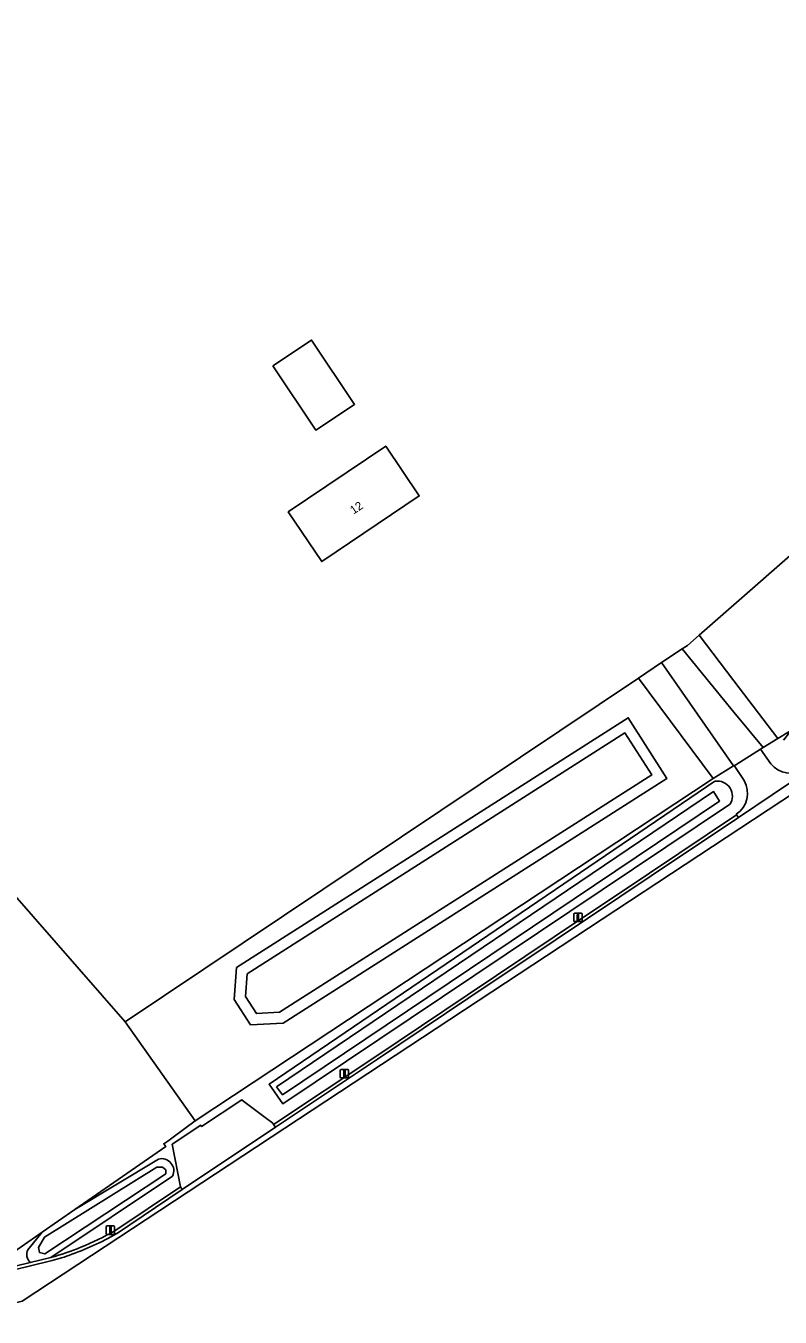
# Model space of a CAD drawing. Extents: x 156502 to 159075, y 384229 to 386100.
# Drawn here: x 158415.4 to 158505.5, y 384265.4 to 384419.7 of the extents above; entities that cross this region are included whole.
import ezdxf

# ---------------------------------------------------------------- set-up
doc = ezdxf.new("R2010")
doc.units = 0
for name, color, linetype in [('IMGEO_Berm_groen', 7, 'Continuous'), ('IMGEO_Gemengd_bos', 7, 'Continuous'), ('IMGEO_Grasland_overig', 7, 'Continuous'), ('IMGEO_Groenvoorziening', 7, 'Continuous'), ('IMGEO_Hek', 7, 'Continuous'), ('IMGEO_Lichtmast', 7, 'Continuous'), ('IMGEO_Loofbos', 7, 'Continuous'), ('IMGEO_Oever', 7, 'Continuous'), ('IMGEO_Pand', 7, 'Continuous'), ('IMGEO_Pand_nummerreeks', 7, 'Continuous'), ('IMGEO_Rijbaan_lokaal_gesloten', 7, 'Continuous'), ('IMGEO_Rijbaan_lokaal_halfverhard', 7, 'Continuous'), ('IMGEO_Rijbaan_lokaal_open', 7, 'Continuous'), ('IMGEO_Waterloop', 7, 'Continuous')]:
    doc.layers.add(name, color=color, linetype=linetype)

msp = doc.modelspace()

# ---------------------------------------------------------------- linework, layer by layer
at = {"layer": 'IMGEO_Berm_groen'}
for points in [[(158501.22, 384329.54), (158500.02, 384331.33), (158499.95, 384331.29), (158497.53, 384329.78), (158435.63, 384288.89), (158435.15, 384288.53), (158434.85, 384288.31), (158432.37, 384286.47), (158431.87, 384286.14), (158432.11, 384285.8), (158421.25, 384278.29), (158431.23, 384284.32)], [(158444.44, 384293.26), (158497.73, 384329.47)], [(158499.48, 384326.68), (158446.11, 384290.9), (158444.44, 384293.26)], [(158457.2, 384296.58), (158468.1, 384303.9), (158478.52, 384310.87), (158489.9, 384318.5), (158500.3, 384325.46), (158500.27, 384325.52)], [(158426.03, 384275.74), (158433.85, 384280.99), (158433.88, 384281.01), (158432.85, 384286.08), (158436.28, 384288.36), (158436.39, 384288.2), (158441.18, 384291.39), (158441.42, 384291.21), (158443.84, 384289.39), (158444.89, 384288.59), (158444.99, 384288.46), (158457.2, 384296.58)], [(158432.91, 384282.29), (158418.39, 384272.56)]]:
    msp.add_lwpolyline(points, dxfattribs=at)
for centre, radius, start, end in [((158498.02, 384327.7), 1.79, 325.0453, 99.1903), ((158498.6, 384328.04), 3.02, 303.4638, 29.7821), ((158431.6, 384282.91), 1.46, 334.556, 104.5546), ((158409.55, 384304.56), 33.19, 291.9275, 299.7688), ((158409.54, 384304.51), 33.15, 285.4732, 291.9749)]:
    msp.add_arc(centre, radius, start, end, dxfattribs=at)
at = {"layer": 'IMGEO_Gemengd_bos'}
msp.add_lwpolyline([(158378.03, 384357.05), (158427.25, 384300.73), (158488.58, 384341.8), (158491.32, 384343.65), (158493.82, 384345.29), (158494.46, 384345.69), (158495.84, 384346.91), (158500, 384350.54), (158541.01, 384386.46), (158573.19, 384414.32), (158670.56, 384500)], dxfattribs=at)
for points in [[(158444.9, 384379.1), (158449.53, 384382.18), (158454.66, 384374.5), (158450.04, 384371.41)], [(158458.38, 384369.51), (158462.39, 384363.57), (158450.74, 384355.71), (158446.73, 384361.65)]]:
    msp.add_lwpolyline(points, close=True, dxfattribs=at)
at = {"layer": 'IMGEO_Grasland_overig'}
msp.add_lwpolyline([(158493.82, 384345.29), (158491.32, 384343.65), (158499.95, 384331.29), (158500.02, 384331.33), (158500.2, 384331.44), (158503.18, 384333.29), (158503.28, 384333.36), (158503.48, 384333.48), (158500, 384337.74)], close=True, dxfattribs=at)
at = {"layer": 'IMGEO_Groenvoorziening'}
for points in [[(158415.64, 384273.48), (158417.33, 384275.58), (158412.28, 384272.08), (158369.4, 384300.97), (158363.15, 384305.15), (158355.76, 384308.75), (158353, 384310.09), (158330.57, 384320.99), (158316.87, 384327), (158310.78, 384329.66), (158301.4, 384333.78), (158224.68, 384367.19), (158139.02, 384415.66), (158112.87, 384430.01), (158110.98, 384431.04), (158010.38, 384485.78)], [(158505.9, 384334.39), (158506.68, 384335.32), (158506.55, 384335.39), (158505.25, 384334.58), (158503.48, 384333.48), (158503.28, 384333.36), (158503.18, 384333.29), (158504.41, 384331.54)], [(158384.23, 384284.06), (158389.27, 384280.37), (158399.37, 384272.71), (158404.11, 384269.44), (158404.62, 384269.18), (158407.37, 384269.88), (158415.91, 384271.95)]]:
    msp.add_lwpolyline(points, dxfattribs=at)
for points in [[(158584.38, 384386.89), (158587.8, 384389.16), (158587.72, 384389.57), (158587.44, 384391.07), (158586.13, 384393.74), (158574.92, 384411.58), (158573.19, 384414.32), (158541.01, 384386.46), (158500, 384350.54), (158495.84, 384346.91), (158500, 384341.46), (158505.25, 384334.58), (158506.55, 384335.39), (158506.68, 384335.32)], [(158505.25, 384334.58), (158500, 384341.46), (158495.84, 384346.91), (158494.46, 384345.69), (158493.82, 384345.29), (158500, 384337.74), (158503.48, 384333.48)], [(158499.95, 384331.29), (158491.32, 384343.65), (158488.58, 384341.8), (158497.53, 384329.78)], [(158497.53, 384329.78), (158488.58, 384341.8), (158427.25, 384300.73), (158435.63, 384288.89)], [(158440.54, 384307.2), (158487.36, 384337.06), (158491.99, 384329.81), (158446.13, 384300.57), (158442.23, 384300.34), (158440.29, 384303.39)]]:
    msp.add_lwpolyline(points, close=True, dxfattribs=at)
for centre, radius, start, end in [((158506.74, 384333.41), 2.98, 218.6163, 303.3303), ((158416.81, 384272.9), 1.31, 153.4915, 226.6054)]:
    msp.add_arc(centre, radius, start, end, dxfattribs=at)
at = {"layer": 'IMGEO_Hek'}
for points in [[(158495.84, 384346.91), (158500, 384350.54), (158541.01, 384386.46), (158573.19, 384414.32)], [(158500, 384341.46), (158495.84, 384346.91)], [(158491.32, 384343.65), (158488.58, 384341.8)], [(158427.25, 384300.73), (158488.58, 384341.8)], [(158497.53, 384329.78), (158488.58, 384341.8)], [(158500, 384341.46), (158505.25, 384334.58)], [(158505.25, 384334.58), (158503.48, 384333.48)], [(158506.68, 384335.32), (158506.55, 384335.39), (158505.25, 384334.58)], [(158503.28, 384333.36), (158503.18, 384333.29), (158500.2, 384331.44)], [(158503.48, 384333.48), (158503.28, 384333.36)], [(158497.53, 384329.78), (158499.95, 384331.29)], [(158500.2, 384331.44), (158500.02, 384331.33), (158499.95, 384331.29)], [(158421.25, 384278.29), (158432.11, 384285.8), (158431.87, 384286.14), (158432.37, 384286.47), (158434.85, 384288.31), (158435.15, 384288.53), (158435.63, 384288.89), (158497.53, 384329.78)], [(158435.63, 384288.89), (158427.25, 384300.73)], [(158417.33, 384275.58), (158421.25, 384278.29)], [(158412.28, 384272.08), (158417.33, 384275.58)]]:
    msp.add_lwpolyline(points, dxfattribs=at)
at = {"layer": 'IMGEO_Lichtmast'}
for p, q in [((158480.86, 384312.79), (158480.86, 384313.59)), ((158480.86, 384313.59), (158480.86, 384312.79)), ((158480.96, 384313.69), (158481.75, 384313.69)), ((158481.75, 384313.69), (158480.96, 384313.69)), ((158481.75, 384312.69), (158480.96, 384312.69)), ((158480.96, 384312.69), (158481.75, 384312.69)), ((158481.85, 384313.59), (158481.85, 384312.79)), ((158481.85, 384312.79), (158481.85, 384313.59)), ((158452.96, 384294.11), (158452.96, 384294.9)), ((158452.96, 384294.9), (158452.96, 384294.11)), ((158453.06, 384295), (158453.85, 384295)), ((158453.85, 384295), (158453.06, 384295)), ((158453.95, 384294.9), (158453.95, 384294.11)), ((158453.95, 384294.11), (158453.95, 384294.9)), ((158453.85, 384294.01), (158453.06, 384294.01)), ((158453.06, 384294.01), (158453.85, 384294.01)), ((158424.99, 384275.42), (158424.99, 384276.22)), ((158424.99, 384276.22), (158424.99, 384275.42)), ((158425.09, 384276.32), (158425.88, 384276.32)), ((158425.88, 384276.32), (158425.09, 384276.32)), ((158425.98, 384276.22), (158425.98, 384275.42)), ((158425.98, 384275.42), (158425.98, 384276.22)), ((158425.88, 384275.32), (158425.09, 384275.32)), ((158425.09, 384275.32), (158425.88, 384275.32))]:
    msp.add_line(p, q, dxfattribs=at)
for points in [[(158481.28, 384313.56), (158481.43, 384313.56), (158481.43, 384312.81), (158481.28, 384312.81), (158481.28, 384313.56)], [(158453.38, 384294.88), (158453.53, 384294.88), (158453.53, 384294.13), (158453.38, 384294.13), (158453.38, 384294.88)], [(158425.41, 384276.2), (158425.56, 384276.2), (158425.56, 384275.45), (158425.41, 384275.45), (158425.41, 384276.2)]]:
    msp.add_lwpolyline(points, dxfattribs=at)
for centre, start, end in [((158480.96, 384313.59), 90, 180), ((158480.96, 384313.59), 90, 180), ((158480.96, 384312.79), 180, 270), ((158480.96, 384312.79), 180, 270), ((158481.75, 384313.59), 0, 90), ((158481.75, 384313.59), 360, 90), ((158481.75, 384312.79), 270, 0), ((158481.75, 384312.79), 270, 0), ((158453.06, 384294.9), 90, 180), ((158453.06, 384294.9), 90, 180), ((158453.06, 384294.11), 180, 270), ((158453.06, 384294.11), 180, 270), ((158453.85, 384294.9), 0, 90), ((158453.85, 384294.9), 360, 90), ((158453.85, 384294.11), 270, 0), ((158453.85, 384294.11), 270, 0), ((158425.09, 384276.22), 90, 180), ((158425.09, 384276.22), 90, 180), ((158425.88, 384276.22), 0, 90), ((158425.88, 384276.22), 360, 90), ((158425.09, 384275.42), 180, 270), ((158425.09, 384275.42), 180, 270), ((158425.88, 384275.42), 270, 0), ((158425.88, 384275.42), 270, 0)]:
    msp.add_arc(centre, 0.1, start, end, dxfattribs=at)
at = {"layer": 'IMGEO_Loofbos'}
msp.add_lwpolyline([(158412.28, 384272.08), (158417.33, 384275.58), (158421.25, 384278.29), (158432.11, 384285.8), (158431.87, 384286.14), (158432.37, 384286.47), (158434.85, 384288.31), (158435.15, 384288.53), (158435.63, 384288.89), (158427.25, 384300.73), (158378.03, 384357.05)], dxfattribs=at)
at = {"layer": 'IMGEO_Oever'}
for points in [[(158440.54, 384307.2), (158440.29, 384303.39), (158442.23, 384300.34), (158446.13, 384300.57), (158491.99, 384329.81), (158487.36, 384337.06)], [(158441.81, 384306.45), (158486.96, 384335.24), (158490.17, 384330.22), (158445.71, 384301.87), (158442.93, 384301.7), (158441.63, 384303.73)], [(158445.35, 384292.94), (158497.56, 384328.24), (158498.28, 384327.1), (158446.07, 384292)], [(158417.63, 384275), (158431.03, 384283.35), (158431.73, 384283.35), (158432.11, 384283.01), (158432.11, 384282.57), (158417.65, 384272.99), (158417, 384273.16), (158416.9, 384273.75)]]:
    msp.add_lwpolyline(points, close=True, dxfattribs=at)
for points in [[(158497.73, 384329.47), (158444.44, 384293.26), (158446.11, 384290.9), (158499.48, 384326.68)], [(158431.23, 384284.32), (158421.25, 384278.29), (158417.33, 384275.58), (158415.64, 384273.48)], [(158415.91, 384271.95), (158418.39, 384272.56), (158432.91, 384282.29)]]:
    msp.add_lwpolyline(points, dxfattribs=at)
for centre, radius, start, end in [((158498.02, 384327.7), 1.79, 325.0453, 99.1903), ((158431.6, 384282.91), 1.46, 334.556, 104.5546), ((158416.81, 384272.9), 1.31, 153.4915, 226.6054)]:
    msp.add_arc(centre, radius, start, end, dxfattribs=at)
at = {"layer": 'IMGEO_Pand'}
for points in [[(158444.9, 384379.1), (158450.04, 384371.41), (158454.66, 384374.5), (158449.53, 384382.18)], [(158450.74, 384355.71), (158462.39, 384363.57), (158458.38, 384369.51), (158446.73, 384361.65)]]:
    msp.add_lwpolyline(points, close=True, dxfattribs=at)
at = {"layer": 'IMGEO_Rijbaan_lokaal_gesloten'}
for points in [[(158543.65, 384352.09), (158542.79, 384353.39), (158532.53, 384346.56), (158521.79, 384339.38), (158508.58, 384330.54), (158500.53, 384325.13), (158490.12, 384318.17), (158478.74, 384310.54), (158468.33, 384303.57), (158457.42, 384296.24), (158445.21, 384288.12), (158434.07, 384280.66), (158426.23, 384275.4)], [(158407.35, 384265.42), (158412.42, 384266.69), (158414.94, 384267.32), (158543.65, 384352.09)], [(158418.22, 384272.1), (158407.46, 384269.49), (158404.77, 384268.81), (158404.62, 384269.18), (158404.11, 384269.44), (158400.41, 384268.15), (158400.38, 384267.91), (158400.32, 384267.46), (158397.14, 384266.24)]]:
    msp.add_lwpolyline(points, dxfattribs=at)
for centre, radius, start, end in [((158409.43, 384304.82), 33.88, 289.1007, 299.7359), ((158409.57, 384304.41), 33.45, 284.99, 289.0995)]:
    msp.add_arc(centre, radius, start, end, dxfattribs=at)
at = {"layer": 'IMGEO_Rijbaan_lokaal_halfverhard'}
msp.add_lwpolyline([(158500.53, 384325.13), (158500.3, 384325.46), (158489.9, 384318.5), (158478.52, 384310.87), (158468.1, 384303.9), (158457.2, 384296.58), (158444.99, 384288.46), (158445.21, 384288.12), (158457.42, 384296.24), (158468.33, 384303.57), (158478.74, 384310.54), (158490.12, 384318.17)], close=True, dxfattribs=at)
for points in [[(158434.07, 384280.66), (158433.88, 384280.99), (158433.88, 384281.01), (158433.85, 384280.99), (158426.03, 384275.74)], [(158426.23, 384275.4), (158434.07, 384280.66)], [(158418.39, 384272.56), (158415.91, 384271.95), (158407.37, 384269.88), (158404.62, 384269.18), (158404.77, 384268.81), (158407.46, 384269.49), (158418.22, 384272.1)]]:
    msp.add_lwpolyline(points, dxfattribs=at)
for centre, radius, start, end in [((158409.55, 384304.56), 33.19, 291.9275, 299.7688), ((158409.43, 384304.82), 33.88, 289.1007, 299.7359), ((158409.57, 384304.41), 33.45, 284.99, 289.0995), ((158409.54, 384304.51), 33.15, 285.4732, 291.9749)]:
    msp.add_arc(centre, radius, start, end, dxfattribs=at)
at = {"layer": 'IMGEO_Rijbaan_lokaal_open'}
for points in [[(158504.41, 384331.54), (158503.18, 384333.29), (158500.2, 384331.44), (158500.02, 384331.33), (158501.22, 384329.54)], [(158500.27, 384325.52), (158500.3, 384325.46), (158500.53, 384325.13), (158508.58, 384330.54), (158508.39, 384330.9), (158508.38, 384330.91)]]:
    msp.add_lwpolyline(points, dxfattribs=at)
msp.add_lwpolyline([(158445.21, 384288.12), (158444.99, 384288.46), (158444.89, 384288.59), (158443.84, 384289.39), (158441.42, 384291.21), (158441.18, 384291.39), (158436.39, 384288.2), (158436.28, 384288.36), (158432.85, 384286.08), (158433.88, 384281.01), (158433.88, 384280.99), (158434.07, 384280.66)], close=True, dxfattribs=at)
for centre, radius, start, end in [((158506.74, 384333.41), 2.98, 218.6163, 303.3303), ((158498.6, 384328.04), 3.02, 303.4638, 29.7821)]:
    msp.add_arc(centre, radius, start, end, dxfattribs=at)
at = {"layer": 'IMGEO_Waterloop'}
for points in [[(158441.81, 384306.45), (158441.63, 384303.73), (158442.93, 384301.7), (158445.71, 384301.87), (158490.17, 384330.22), (158486.96, 384335.24)], [(158445.35, 384292.94), (158446.07, 384292), (158498.28, 384327.1), (158497.56, 384328.24)], [(158416.9, 384273.75), (158417, 384273.16), (158417.65, 384272.99), (158432.11, 384282.57), (158432.11, 384283.01), (158431.73, 384283.35), (158431.03, 384283.35), (158417.63, 384275)]]:
    msp.add_lwpolyline(points, close=True, dxfattribs=at)

# ---------------------------------------------------------------- texts
at = {"layer": 'IMGEO_Pand_nummerreeks'}
msp.add_text('12', height=1, rotation=34.0068, dxfattribs=at).set_placement((158454.54, 384361.32))

doc.saveas('drawing.dxf')
